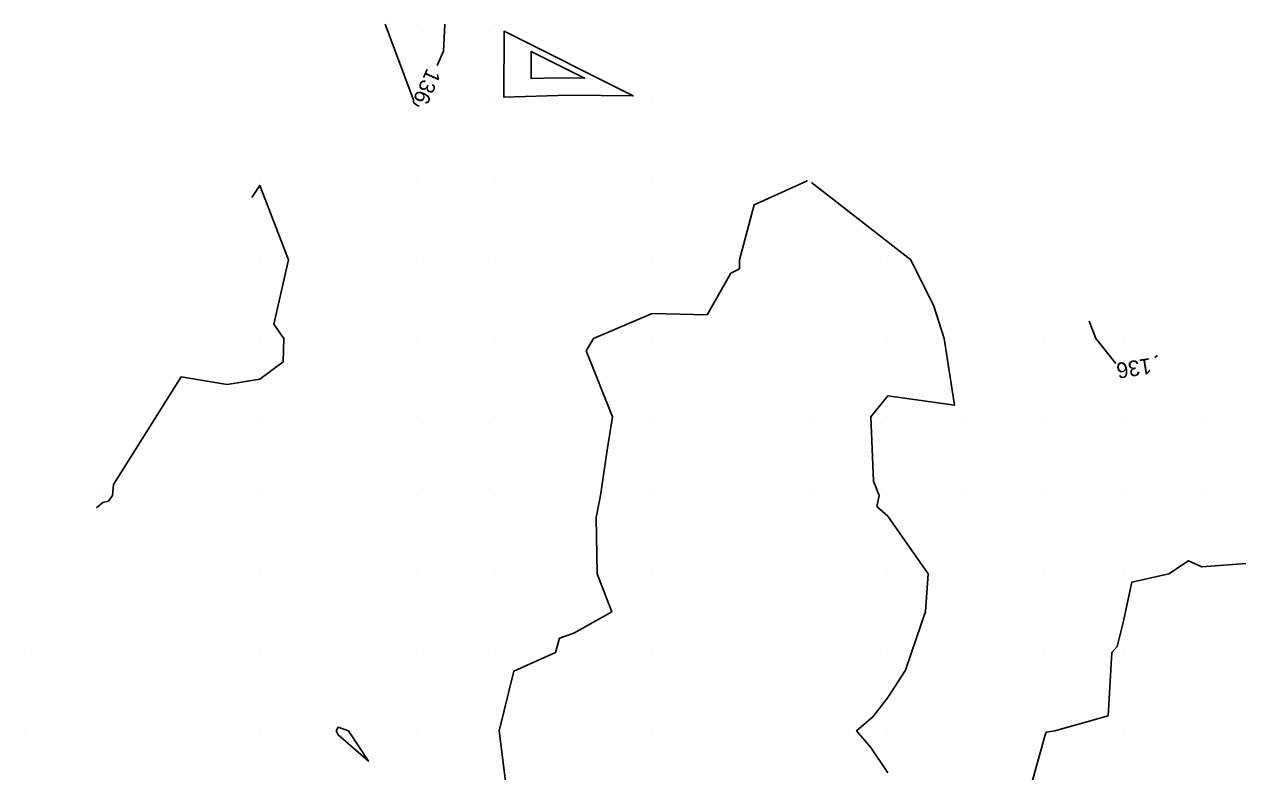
# Model space of a CAD drawing. Extents: x 2354170 to 2357230, y 866100 to 868290.
# Drawn here: x 2354360 to 2354514.6, y 868044.8 to 868140 of the extents above; entities that cross this region are included whole.
import ezdxf

# ---------------------------------------------------------------- set-up
doc = ezdxf.new("R2010")
doc.units = 0
for name, color, linetype in [('Default', 7, 'Continuous'), ('DTM Contours Minor', 7, 'Continuous'), ('DTM Contours Minor Text', 7, 'Continuous'), ('Exist DTM QL2 LIDAR Elevation Point', 7, 'Continuous')]:
    doc.layers.add(name, color=color, linetype=linetype)

msp = doc.modelspace()

# ---------------------------------------------------------------- linework, layer by layer
at = {"layer": 'Default'}
for points in [[(2354429.35, 868131.01), (2354437.54, 868130.9), (2354421.11, 868139.16), (2354421.04, 868130.75), (2354429.35, 868131.01)], [(2354427.96, 868133.21), (2354431.34, 868133.16), (2354424.56, 868136.57), (2354424.54, 868133.1), (2354427.96, 868133.21)], [(2354369.17, 868078.44), (2354369.96, 868079.11), (2354370.69, 868079.3), (2354371.22, 868080.02), (2354371.34, 868081.4), (2354379.96, 868095.12), (2354385.83, 868094.16), (2354389.96, 868094.83), (2354392.96, 868097.03), (2354393.05, 868100.02), (2354391.76, 868101.82), (2354393.64, 868110.02), (2354389.96, 868119.49), (2354388.94, 868117.97)], [(2354459.74, 868120.14), (2354459.52, 868120.02), (2354452.96, 868117.03), (2354451.07, 868110.02), (2354451.09, 868108.89), (2354449.96, 868108.32), (2354446.97, 868103.02), (2354439.96, 868103.18), (2354432.47, 868100.02), (2354431.55, 868098.43), (2354434.88, 868090.02), (2354434.23, 868085.76), (2354433.37, 868080.02), (2354432.8, 868077.19), (2354432.95, 868070.02), (2354434.8, 868065.19), (2354429.96, 868062.48), (2354428.14, 868061.84), (2354427.65, 868060.02), (2354422.35, 868057.64), (2354420.46, 868050.02), (2354421.54, 868041.6)], [(2354469.97, 868044.68), (2354467.83, 868047.89), (2354465.99, 868050.02), (2354468.12, 868051.87), (2354469.97, 868054.26), (2354472.22, 868057.77), (2354472.98, 868060.02), (2354474.77, 868065.22), (2354475.11, 868070.02), (2354469.97, 868077.36), (2354468.56, 868078.62), (2354468.87, 868080.02), (2354468.16, 868081.82), (2354467.8, 868090.02), (2354469.97, 868092.68), (2354478.49, 868091.5), (2354477.16, 868100.02), (2354475.85, 868104.14), (2354472.9, 868110.02), (2354460.26, 868119.88)], [(2354518.42, 868071.57), (2354509.97, 868070.9), (2354508.29, 868071.7), (2354505.77, 868070.02), (2354501.04, 868068.95), (2354499.97, 868063.84), (2354499.2, 868060.79), (2354498.5, 868060.02), (2354498.03, 868051.96), (2354491.27, 868050.02), (2354490.13, 868049.85), (2354489.97, 868049.36), (2354487.95, 868042.04)], [(2354399.69, 868050.02), (2354399.96, 868050.49), (2354401.26, 868050.02), (2354403.82, 868046.17), (2354399.96, 868049.52), (2354399.69, 868050.02)]]:
    msp.add_lwpolyline(points, dxfattribs=at)
at = {"layer": 'DTM Contours Minor'}
for points in [[(2354405.95, 868140.02), (2354409.49, 868130.49), (2354409.61, 868130.02), (2354409.96, 868129.72), (2354410.25, 868129.61)], [(2354412.55, 868134.79), (2354413.39, 868136.59), (2354413.54, 868140.02)], [(2354495.61, 868102.2), (2354496.48, 868100.02), (2354499.02, 868096.81)], [(2354503.98, 868097.58), (2354504.35, 868097.83)]]:
    msp.add_lwpolyline(points, dxfattribs=at)
at = {"layer": 'Exist DTM QL2 LIDAR Elevation Point'}
for p, q in [((2354399.96, 868140.02), (2354399.96, 868140.02)), ((2354409.96, 868140.02), (2354409.96, 868140.02)), ((2354419.96, 868140.02), (2354419.96, 868140.02)), ((2354426.99, 868134.75), (2354426.99, 868134.75)), ((2354399.96, 868130.02), (2354399.96, 868130.02)), ((2354409.96, 868130.02), (2354409.96, 868130.02)), ((2354419.96, 868130.02), (2354419.96, 868130.02)), ((2354429.96, 868130.02), (2354429.96, 868130.02)), ((2354439.96, 868130.02), (2354439.96, 868130.02)), ((2354389.96, 868120.02), (2354389.96, 868120.02)), ((2354399.96, 868120.02), (2354399.96, 868120.02)), ((2354409.96, 868120.02), (2354409.96, 868120.02)), ((2354419.96, 868120.02), (2354419.96, 868120.02)), ((2354429.96, 868120.02), (2354429.96, 868120.02)), ((2354439.96, 868120.02), (2354439.96, 868120.02)), ((2354449.96, 868120.02), (2354449.96, 868120.02)), ((2354459.96, 868120.02), (2354459.96, 868120.02)), ((2354389.96, 868110.02), (2354389.96, 868110.02)), ((2354399.96, 868110.02), (2354399.96, 868110.02)), ((2354409.96, 868110.02), (2354409.96, 868110.02)), ((2354419.96, 868110.02), (2354419.96, 868110.02)), ((2354429.96, 868110.02), (2354429.96, 868110.02)), ((2354439.96, 868110.02), (2354439.96, 868110.02)), ((2354449.96, 868110.02), (2354449.96, 868110.02)), ((2354459.96, 868110.02), (2354459.96, 868110.02)), ((2354469.97, 868110.02), (2354469.97, 868110.02)), ((2354479.97, 868110.02), (2354479.97, 868110.02)), ((2354379.96, 868100.02), (2354379.96, 868100.02)), ((2354389.96, 868100.02), (2354389.96, 868100.02)), ((2354399.96, 868100.02), (2354399.96, 868100.02)), ((2354409.96, 868100.02), (2354409.96, 868100.02)), ((2354419.96, 868100.02), (2354419.96, 868100.02)), ((2354429.96, 868100.02), (2354429.96, 868100.02)), ((2354439.96, 868100.02), (2354439.96, 868100.02)), ((2354449.96, 868100.02), (2354449.96, 868100.02)), ((2354459.96, 868100.02), (2354459.96, 868100.02)), ((2354469.97, 868100.02), (2354469.97, 868100.02)), ((2354479.97, 868100.02), (2354479.97, 868100.02)), ((2354489.97, 868100.02), (2354489.97, 868100.02)), ((2354499.97, 868100.02), (2354499.97, 868100.02)), ((2354379.96, 868090.02), (2354379.96, 868090.02)), ((2354389.96, 868090.02), (2354389.96, 868090.02)), ((2354399.96, 868090.02), (2354399.96, 868090.02)), ((2354409.96, 868090.02), (2354409.96, 868090.02)), ((2354419.96, 868090.02), (2354419.96, 868090.02)), ((2354429.96, 868090.02), (2354429.96, 868090.02)), ((2354439.96, 868090.02), (2354439.96, 868090.02)), ((2354449.96, 868090.02), (2354449.96, 868090.02)), ((2354459.96, 868090.02), (2354459.96, 868090.02)), ((2354469.97, 868090.02), (2354469.97, 868090.02)), ((2354479.97, 868090.02), (2354479.97, 868090.02)), ((2354489.97, 868090.02), (2354489.97, 868090.02)), ((2354499.97, 868090.02), (2354499.97, 868090.02)), ((2354509.97, 868090.02), (2354509.97, 868090.02)), ((2354369.96, 868080.02), (2354369.96, 868080.02)), ((2354379.96, 868080.02), (2354379.96, 868080.02)), ((2354389.96, 868080.02), (2354389.96, 868080.02)), ((2354399.96, 868080.02), (2354399.96, 868080.02)), ((2354409.96, 868080.02), (2354409.96, 868080.02)), ((2354419.96, 868080.02), (2354419.96, 868080.02)), ((2354429.96, 868080.02), (2354429.96, 868080.02)), ((2354439.96, 868080.02), (2354439.96, 868080.02)), ((2354449.96, 868080.02), (2354449.96, 868080.02)), ((2354459.96, 868080.02), (2354459.96, 868080.02)), ((2354469.97, 868080.02), (2354469.97, 868080.02)), ((2354479.97, 868080.02), (2354479.97, 868080.02)), ((2354489.97, 868080.02), (2354489.97, 868080.02)), ((2354499.97, 868080.02), (2354499.97, 868080.02)), ((2354509.97, 868080.02), (2354509.97, 868080.02)), ((2354369.96, 868070.02), (2354369.96, 868070.02)), ((2354379.96, 868070.02), (2354379.96, 868070.02)), ((2354389.96, 868070.02), (2354389.96, 868070.02)), ((2354399.96, 868070.02), (2354399.96, 868070.02)), ((2354409.96, 868070.02), (2354409.96, 868070.02)), ((2354419.96, 868070.02), (2354419.96, 868070.02)), ((2354429.96, 868070.02), (2354429.96, 868070.02)), ((2354439.96, 868070.02), (2354439.96, 868070.02)), ((2354449.96, 868070.02), (2354449.96, 868070.02)), ((2354459.96, 868070.02), (2354459.96, 868070.02)), ((2354469.97, 868070.02), (2354469.97, 868070.02)), ((2354479.97, 868070.02), (2354479.97, 868070.02)), ((2354489.97, 868070.02), (2354489.97, 868070.02)), ((2354499.97, 868070.02), (2354499.97, 868070.02)), ((2354509.97, 868070.02), (2354509.97, 868070.02)), ((2354359.96, 868060.02), (2354359.96, 868060.02)), ((2354369.96, 868060.02), (2354369.96, 868060.02)), ((2354379.96, 868060.02), (2354379.96, 868060.02)), ((2354389.96, 868060.02), (2354389.96, 868060.02)), ((2354399.96, 868060.02), (2354399.96, 868060.02)), ((2354409.96, 868060.02), (2354409.96, 868060.02)), ((2354419.96, 868060.02), (2354419.96, 868060.02)), ((2354429.96, 868060.02), (2354429.96, 868060.02)), ((2354439.96, 868060.02), (2354439.96, 868060.02)), ((2354449.96, 868060.02), (2354449.96, 868060.02)), ((2354459.96, 868060.02), (2354459.96, 868060.02)), ((2354469.97, 868060.02), (2354469.97, 868060.02)), ((2354479.97, 868060.02), (2354479.97, 868060.02)), ((2354489.97, 868060.02), (2354489.97, 868060.02)), ((2354499.97, 868060.02), (2354499.97, 868060.02)), ((2354509.97, 868060.02), (2354509.97, 868060.02)), ((2354359.96, 868050.02), (2354359.96, 868050.02)), ((2354369.96, 868050.02), (2354369.96, 868050.02)), ((2354379.96, 868050.02), (2354379.96, 868050.02)), ((2354389.96, 868050.02), (2354389.96, 868050.02)), ((2354399.96, 868050.02), (2354399.96, 868050.02)), ((2354409.96, 868050.02), (2354409.96, 868050.02)), ((2354419.96, 868050.02), (2354419.96, 868050.02)), ((2354429.96, 868050.02), (2354429.96, 868050.02)), ((2354439.96, 868050.02), (2354439.96, 868050.02)), ((2354449.96, 868050.02), (2354449.96, 868050.02)), ((2354459.96, 868050.02), (2354459.96, 868050.02)), ((2354469.97, 868050.02), (2354469.97, 868050.02)), ((2354479.97, 868050.02), (2354479.97, 868050.02)), ((2354489.97, 868050.02), (2354489.97, 868050.02)), ((2354499.97, 868050.02), (2354499.97, 868050.02)), ((2354509.97, 868050.02), (2354509.97, 868050.02))]:
    msp.add_line(p, q, dxfattribs=at)

# ---------------------------------------------------------------- texts
at = {"layer": 'DTM Contours Minor Text'}
for rotation, p in [(246.0466, (2354411.28, 868134.52)), (188.8852, (2354503.39, 868097.54))]:
    msp.add_text('136', height=2, rotation=rotation, dxfattribs=at).set_placement(p)

doc.saveas('drawing.dxf')
